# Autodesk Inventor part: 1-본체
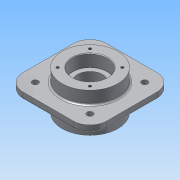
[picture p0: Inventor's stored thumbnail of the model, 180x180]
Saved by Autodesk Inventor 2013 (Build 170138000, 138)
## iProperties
Created: 2015-09
Part Number: 1-본체
Material: 알루미늄 6061
Document SubType Name: Modeling
Designer: dfdfd
Density: 1 g/cm^3
Author: dfdfd
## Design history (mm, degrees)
sketch "스케치3"
  geometry: C1 r 50 at (0, 0); 1 further point
  constraints: 1 centre point, 1 coincident
  dimensions: "d4" = 100 diameter of C1
extrude "돌출2" new body sketch "스케치3" distance "d6" = 70; taper "d7" = 0 deg
node "작업 평면2"
sketch "스케치4"
  geometry: L1 (-75, -75)-(75, -75); L2 (75, -75)-(75, 75); L3 (75, 75)-(-75, 75); L4 (-75, 75)-(-75, -75); L5 (-75, -75)-(75, 75); L6 (75, -75)-(-75, 75); 1 further point
  constraints: 12 end point, 2 midpoint, 2 parallel, 2 perpendicular, 1 horizontal
  dimensions: "d9" = 150 distance of L2.end L3.end
extrude "돌출3" join sketch "스케치4" distance "d11" = 12; taper "d12" = 0 deg
hole "구멍1" diameter "d15" = 45; stored, may be unused: countersink angle "d19" = 90 deg, drill point angle "d21" = 118 deg; dims "d13" = 10, "d14" = 10, "d16" = 6, "d17" = 62, "d18" = 22, "d20" = 8
hole "구멍2" diameter "d24" = 45; stored, may be unused: countersink angle "d28" = 90 deg, drill point angle "d30" = 118 deg; dims "d22" = 10, "d23" = 10, "d25" = 6, "d26" = 62, "d27" = 22, "d29" = 8
sketch "스케치5"
  geometry: L1 (49, 49)-(49, -49); L2 (49, -49)-(-49, -49); L3 (-49, -49)-(-49, 49); L4 (-49, 49)-(49, 49); C1 r 50 at (0, 0) reference; C2 r 10 at (49, 49); C3 r 10 at (-49, 49); C4 r 10 at (-49, -49); C5 r 10 at (49, -49); 1 further point
  constraints: 8 end point, 5 coincident, 4 centre point, 3 equal radius, 1 horizontal, 9 other
  dimensions: "d31" = 98 distance of L3.end L1.start; "d33" = 20 diameter of C3
extrude "돌출4" join sketch "스케치5" distance "d34" = 5; taper "d35" = 0 deg
sketch "스케치6"
  geometry: C1 r 10 at (0, 0) reference; C2 r 10 at (-98, 98) reference; C3 r 10 at (0, 98) reference; C4 r 10 at (-98, 0) reference; 5 further points
  constraints: 4 coincident
hole "구멍3" sketch "스케치6" at (-98, 98), (0, 98), (0, 0), (-98, 0) diameter "d36" = 11; stored, may be unused: countersink angle "d40" = 90 deg, drill point angle "d42" = 118 deg; dims "d37" = 6, "d38" = 62, "d39" = 22, "d41" = 8
sketch "스케치7"
  geometry: L1 (28.991, 28.991)-(28.991, -28.991); L2 (28.991, -28.991)-(-28.991, -28.991); L3 (-28.991, -28.991)-(-28.991, 28.991); L4 (-28.991, 28.991)-(28.991, 28.991); C1 r 50 at (0, 0) reference; 5 further points
  constraints: 8 end point, 5 coincident, 1 horizontal, 9 other
  dimensions: "d43" = 82 distance of L2.end L1.start
hole "구멍4" sketch "스케치7" at (28.991, 28.991), (-28.991, 28.991), (-28.991, -28.991), (28.991, -28.991) diameter "d44" = 4.917; stored, may be unused: countersink angle "d48" = 90 deg, drill point angle "d50" = 118 deg; dims "d45" = 10, "d46" = 62, "d47" = 22, "d49" = 13
node "작업 평면3"
fillet "모깎기1" dims "d51" = 30, "d52" = 0.3
chamfer "모따기1" distance "d53" = 1; stored, may be unused: second distance "d54" = 2, angle "d55" = 45 deg
fillet "모깎기2" dims "d56" = 3
sketch "스케치8"
  geometry: C1 r 53 at (0, 0) reference; 1 further point
  constraints: 1 vertical alignment, 1 other
  dimensions: "d57" = 65 distance of point (0, 65) C1.centre
feature "엠보싱1" sketch "스케치8" dims "d58" = 1, "d59" = 0
node "솔리드2"
mirror "대칭1"
node "투영된 루프1"
node "투영된 루프2"
node "투영된 루프3"
other parameters: "d8" = -23
